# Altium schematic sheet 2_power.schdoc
size 309 x 223 mm; Symbol: Sheet-Symbol_A4; Device: Sheet-Symbol_A4; Company: 嘉立创EDA; Version: V1.0; Page Size: A4; @Project Name: fm33; @Page Count: 3; @Update Date: 2025-07-18; @Create Date: 2025-07-15; @Schematic Name: Schematic6; @Page No: 2; @Page Name: power; Title Block Position: 3; Width: 1170; Height: 825; Region Start: 1; X Region Count: 6; Y Region Count: 4; Blade Width: 10; @Board Name: core_3; @Create Time: 10:35:12; @Update Time: 17:10:59
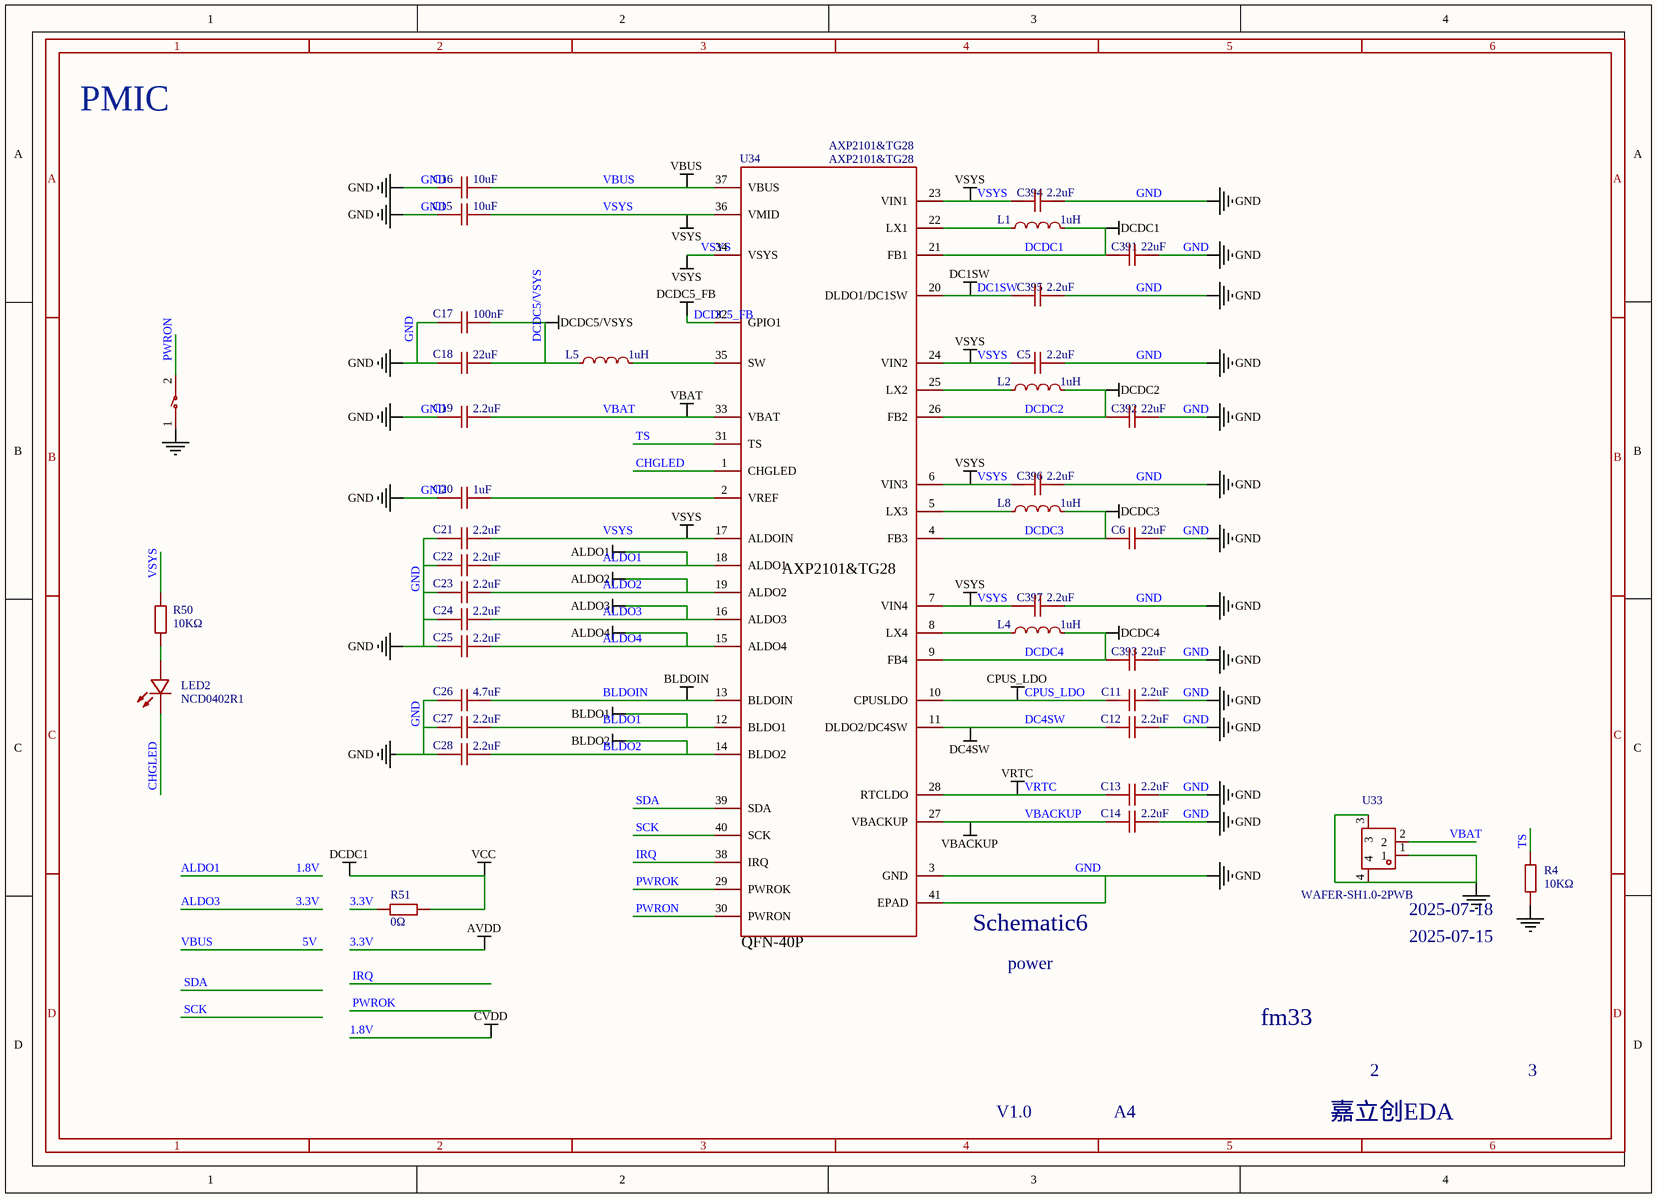
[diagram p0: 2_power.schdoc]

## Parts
C5  2.2uF  [C0603]  (value not drawn)
C6  22uF  [C0603]  (value not drawn)
C11  2.2uF  [C0603]  (value not drawn)
C12  2.2uF  [C0603]  (value not drawn)
C13  2.2uF  [C0603]  (value not drawn)
C14  2.2uF  [C0603]  (value not drawn)
C15  10uF  [C0603]  (value not drawn)
C16  10uF  [C0603]  (value not drawn)
C17  100nF  [C0603]  (value not drawn)
C18  22uF  [C0603]  (value not drawn)
C19  2.2uF  [C0603]  (value not drawn)
C20  1uF  [C0603]  (value not drawn)
C21  2.2uF  [C0603]  (value not drawn)
C22  2.2uF  [C0603]  (value not drawn)
C23  2.2uF  [C0603]  (value not drawn)
C24  2.2uF  [C0603]  (value not drawn)
C25  2.2uF  [C0603]  (value not drawn)
C26  4.7uF  [C0603]  (value not drawn)
C27  2.2uF  [C0603]  (value not drawn)
C28  2.2uF  [C0603]  (value not drawn)
C391  22uF  [C0603]  (value not drawn)
C392  22uF  [C0603]  (value not drawn)
C393  22uF  [C0603]  (value not drawn)
C394  2.2uF  [C0603]  (value not drawn)
C395  2.2uF  [C0603]  (value not drawn)
C396  2.2uF  [C0603]  (value not drawn)
C397  2.2uF  [C0603]  (value not drawn)
L1  1uH  [L0806]  (value not drawn)
L2  1uH  [L0806]  (value not drawn)
L4  1uH  [L0806]  (value not drawn)
L5  1uH  [L0806]  (value not drawn)
L8  1uH  [L0806]  (value not drawn)
LED2  NCD0402R1  [LED0402-RD]  (value not drawn)
R4  10KΩ  [R0402]  (value not drawn)
R50  10KΩ  [R0402]  (value not drawn)
R51  0Ω  [C0603 NSK]  (value not drawn)
U10  THAF09-AC-R  [KEY-SMD_L3.9-W2.9-P4.6-LS5.0-W3.6-EH]  (value not drawn)
U33  WAFER-SH1.0-2PWB  [CONN-SMD_2P-P1.00_XUNPU_WAFER-SH1.0-2PWB]  (value not drawn)
U34  AXP2101&TG28  [QFN-40_L5.0-W5.0-P0.40-TL-EP3.4]

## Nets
1.8V: C22.2 U34.18(ALDO1)  [also labelled ALDO1, CVDD]
3.3V: C24.2 R51.1 U34.16(ALDO3)  [also labelled ALDO3, AVDD]
5V: C16.1 U34.37(VBUS)  [also labelled VBUS]
ALDO2: C23.2 U34.19(ALDO2)
ALDO4: C25.2 U34.15(ALDO4)
BLDO1: C27.2 U34.12(BLDO1)
BLDO2: C28.2 U34.14(BLDO2)
BLDOIN: C26.2 U34.13(BLDOIN)
CPUS_LDO: C11.1 U34.10(CPUSLDO)
DC1SW: C395.1 U34.20(DLDO1/DC1SW)
DC4SW: C12.1 U34.11(DLDO2/DC4SW)
DCDC1: C391.1 L1.2 R51.2 U34.21(FB1)  [also labelled VCC]
DCDC2: C392.1 L2.2 U34.26(FB2)
DCDC3: C6.1 L8.2 U34.4(FB3)
DCDC4: C393.1 L4.2 U34.9(FB4)
DCDC5/VSYS: C17.2 C18.2 L5.1
DCDC5_FB: U34.32(GPIO1)
GND: C5.2 C6.2 C11.2 C12.2 C13.2 C14.2 C15.2 C16.2 C17.1 C18.1 C19.1 C20.1 C21.1 C22.1 C23.1 C24.1 C25.1 C26.1 C27.1 C28.1 C391.2 C392.2 C393.2 C394.2 C395.2 C396.2 C397.2 R4.2 U10.1 U33.1 U33.3 U33.4 U34.3(GND) U34.41(EPAD)
VBACKUP: C14.1 U34.27(VBACKUP)
VBAT: C19.2 U33.2 U34.33(VBAT)
VRTC: C13.1 U34.28(RTCLDO)
VSYS: C5.1 C15.1 C21.2 C394.1 C396.1 C397.1 R50.1 U34.6(VIN3) U34.7(VIN4) U34.17(ALDOIN) U34.23(VIN1) U34.24(VIN2) U34.34(VSYS) U34.36(VMID)
CHGLED: LED2.1(K) U34.1(CHGLED)
IRQ: U34.38(IRQ)
PWROK: U34.29(PWROK)
PWRON: U10.2 U34.30(PWRON)
SCK: U34.40(SCK)
SDA: U34.39(SDA)
TS: R4.1 U34.31(TS)
NetC20_2: C20.2 U34.2(VREF)
NetL1_1: L1.1 U34.22(LX1)
NetL2_1: L2.1 U34.25(LX2)
NetL4_1: L4.1 U34.8(LX4)
NetL5_2: L5.2 U34.35(SW)
NetL8_1: L8.1 U34.5(LX3)
NetLED2_2: LED2.2(A) R50.2

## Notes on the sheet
- PMIC

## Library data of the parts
C5 C11-C14 C19 C21-C25 C27 C28 C394-C397 = CL10A225KP8NNNC: 容值:2.2uF;精度:±10%;额定电压:10V;材质(温度系数):X5R;; Manufacturer: SAMSUNG(三星); Symbol: 2.2uF/0603; Add into BOM: yes; Tolerance: ±10%; Voltage Rated: 10V; Temperature Coefficient: X5R
C6 C18 C391-C393 = CL10A226MQ8NRNC: 容值:22uF;精度:±20%;额定电压:6.3V;材质(温度系数):X5R;; Manufacturer: SAMSUNG(三星); Symbol: 22uF/0603; Add into BOM: yes; Tolerance: ±20%; Voltage Rated: 6.3V; Temperature Coefficient: X5R
C15 C16 = CL10A106KP8NNNC: 容值:10uF;精度:±10%;额定电压:10V;材质(温度系数):X5R;; Manufacturer: SAMSUNG(三星); Symbol: 10uF/0603; Add into BOM: yes; Tolerance: ±10%; Voltage Rated: 10V; Temperature Coefficient: X5R
C17 = CL10B104KB8NNNC: 容值:100nF;精度:±10%;额定电压:50V;材质(温度系数):X7R;; Manufacturer: SAMSUNG(三星); Symbol: 100nF/0603; Add into BOM: yes; Tolerance: ±10%; Voltage Rated: 50V; Temperature Coefficient: X7R
C20 = CL10A105KO8NNNC: 容值:1uF;精度:±10%;额定电压:16V;材质(温度系数):X5R;; Manufacturer: SAMSUNG(三星); Symbol: 1uF/0603; Add into BOM: yes; Tolerance: ±10%; Voltage Rated: 16V; Temperature Coefficient: X5R
C26 = CL10A475KP8NNNC: 容值:4.7uF;精度:±10%;额定电压:10V;材质(温度系数):X5R;; Manufacturer: SAMSUNG(三星); Symbol: 4.7uF/0603; Add into BOM: yes; Tolerance: ±10%; Voltage Rated: 10V; Temperature Coefficient: X5R
L1 L2 L4 L5 L8 = 1uH: Manufacturer: chilisin(奇力新); Manufacturer Part: HEI201610K-1R0M-Q8DG; Convert to PCB: yes
LED2 = NCD0402R1: 发光颜色:红色;正向电压(VF):1.6V~2.6V;功率:65mW;正向电流:5mA;主波长:615nm~635nm;透镜颜色:无色透明透镜;发光强度:13mcd~30mcd;发光角度:130°;工作温度:-30℃~+85℃;; Manufacturer: 国星光电; Symbol: FC-F1005HRK-620H5; Add into BOM: yes; Emitted Color: 红色; Power Dissipation: 65mW; Forward Current: 5mA; Lens Color: 无色透明透镜; Viewing Angle: 130°
R4 R50 = 0402WGF2200TCE: 电阻类型:厚膜电阻;阻值:220Ω;精度:±1%;功率:62.5mW;温度系数:±100ppm/℃;最大工作电压:50V;工作温度范围:-55℃~+155℃;; Manufacturer: UNI-ROYAL(厚声); Add into BOM: yes; Tolerance: ±1%; Power(Watts): 62.5mW; Overload Voltage (Max): 50V
R51 = 0603WAF0000T5E: 电阻类型:厚膜电阻;阻值:0Ω;精度:±1%;功率:100mW;最大工作电压:75V;; Manufacturer: UNI-ROYAL(厚声); Add into BOM: yes; Tolerance: ±1%; Power(Watts): 100mW; Overload Voltage (Max): 75V
U10 = THAF09-AC-R: 按钮形状:方形按钮;作用力:250gf;开关长度:2.9mm;开关宽度:3.9mm;开关高度:1.5mm;带支架:不带;触点电流:50mA;额定电压(AC):250V;额定电压(DC):12V;绝缘电阻:100mΩ;带灯:无;机械寿命:5万次;; Manufacturer: jianfu(键富); Add into BOM: yes; Actuator Style: 方形按钮; Operating Force: 250gf; Switch Length: 2.9mm; Switch Width: 3.9mm; Switch Height: 1.5mm; Strike Gundam: 不带; Contact Current: 50mA; Voltage Rating (AC): 250V; Voltage Rating (DC): 12V; Insulation Resistance: 100mΩ; Actuator/Cap Color: 黑色; With Lamp: 无; Pin Style: SMD接片; Mechanical Life: 5万次
U33 = WAFER-SH1.0-2PWB: 插针结构:1x2P;间距:1mm;安装方式:卧贴;参考系列:SH;总PIN数:2P;排数:1;每排PIN数:2;行距:-;额定电流:1A;触头材质:黄铜;触头镀层:-;工作温度:-25℃~+85℃;; Manufacturer: XUNPU(讯普); Add into BOM: yes; Pins Structure: 1x2P; Pitch: 1mm; Reference Series: SH; Number of PINs Per Row: 2; Current Rating: 1A; Voltage Rating: 50V; Plastic Material: LCP; Supplementary Features: 辅助焊脚; Z-Height of the Board: 3.15mm; X-Length of Bottom Edge on Board (Spacing Line): 4.35mm; Y-Width of Bottom Edge on Board: 5.05mm
U34 = AXP2101: A PMU designed by Allwinner; Manufacturer: x-powers; Add into BOM: yes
